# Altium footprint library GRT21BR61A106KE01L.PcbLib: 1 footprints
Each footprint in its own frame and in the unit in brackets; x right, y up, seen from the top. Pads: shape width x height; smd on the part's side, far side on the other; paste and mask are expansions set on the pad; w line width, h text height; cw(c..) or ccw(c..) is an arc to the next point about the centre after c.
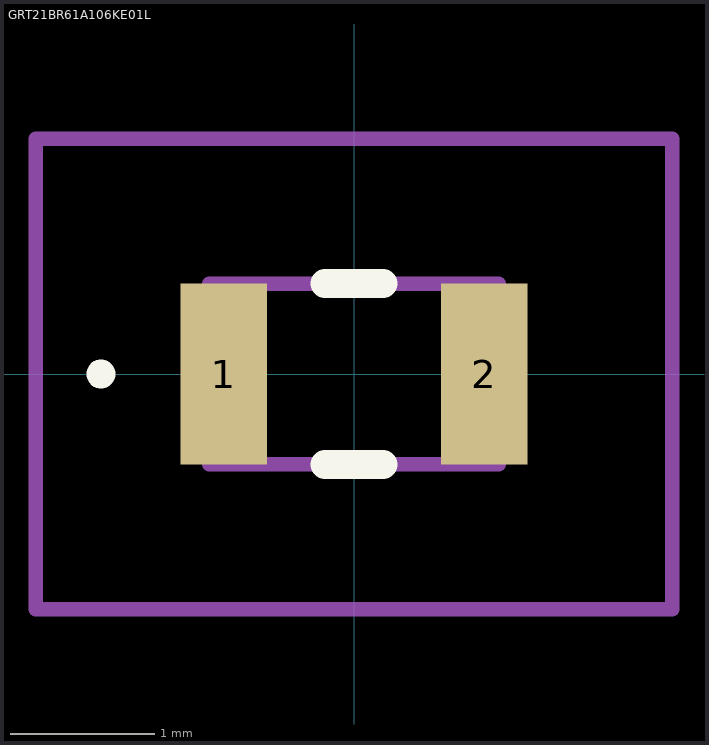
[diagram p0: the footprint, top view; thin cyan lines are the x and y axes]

## GRT21BR61A106KE01L [mm]
pads (2):
  rect 0.6x1.25 smd: 1(-0.9,0) 2(0.9,0)
Top Overlay:
  lines w0.1: -1.8,0 -1.8,0 ; -1.8,0 ccw(c-1.75,0) -1.7,0 ; -1.8,0 cw(c-1.75,0) -1.7,0 ; -1.7,0 -1.7,0
  lines w0.2: -0.2,-0.625 0.2,-0.625 ; -0.2,0.625 0.2,0.625
Mechanical 15:
  lines w0.1: -1,-0.625 1,-0.625 1,0.625 -1,0.625 -1,-0.625
Mechanical 20:
  lines w0.1: -2.2,-1.625 2.2,-1.625 2.2,1.625 -2.2,1.625 -2.2,-1.625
